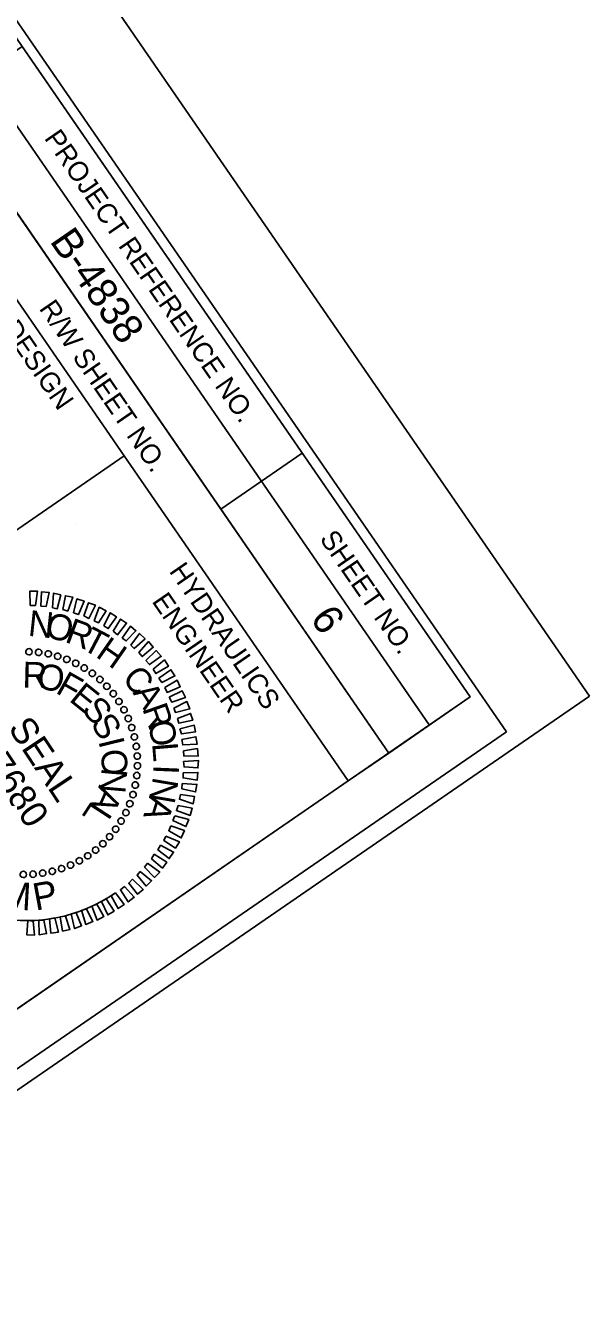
# Model space of a CAD drawing. Extents: x 2297526 to 2298642, y 599613 to 600819.
# Drawn here: x 2298556.7 to 2298642.4, y 599895.5 to 600089.1 of the extents above; entities that cross this region are included whole.
import ezdxf

# ---------------------------------------------------------------- set-up
doc = ezdxf.new("R2010")
doc.units = 0
for name, color, linetype in [('Exist DTM Drainline Cogo Comment', 7, 'Continuous'), ('Exist DTM Drainline Cogo Elevation', 7, 'Continuous'), ('Exist DTM Drainline Cogo Point CELL', 7, 'Continuous'), ('Exist Roads Curbs Cogo Point CELL', 7, 'Continuous'), ('Exist Roads EOP Cogo Point CELL', 7, 'Continuous'), ('Exist Roads Soil Cogo Number', 7, 'Continuous')]:
    doc.layers.add(name, color=color, linetype=linetype)

msp = doc.modelspace()

# ---------------------------------------------------------------- linework, layer by layer
at = {"layer": 'Exist DTM Drainline Cogo Comment'}
msp.add_lwpolyline([(2298629.8, 599981.76), (2298062.67, 600805.27), (2297541.29, 600446.21), (2298108.42, 599622.7)], close=True, dxfattribs=at)
at = {"layer": 'Exist DTM Drainline Cogo Elevation'}
for p, q in [((2298550, 600081.65), (2298618.08, 599982.8)), ((2298543.83, 600077.4), (2298611.91, 599978.54)), ((2298543.83, 600077.4), (2298611.91, 599978.54)), ((2298598.74, 600024.11), (2298586.38, 600015.6)), ((2298611.91, 599978.54), (2298605.73, 599974.29))]:
    msp.add_line(p, q, dxfattribs=at)
for points in [[(2298624.28, 599987.07), (2298113.82, 600728.3), (2297594.96, 600370.97), (2298105.42, 599629.74)], [(2298556.21, 600085.92), (2298624.28, 599987.07), (2298611.91, 599978.54), (2298543.83, 600077.4)], [(2298537.65, 600073.14), (2298571.7, 600023.7), (2298516.11, 599985.42), (2298482.06, 600034.86)], [(2298571.7, 600023.7), (2298605.73, 599974.29), (2298550.14, 599936), (2298516.11, 599985.42)]]:
    msp.add_lwpolyline(points, close=True, dxfattribs=at)
at = {"layer": 'Exist DTM Drainline Cogo Point CELL'}
msp.add_arc((2298556.8, 599977.02), 23.96, 124.5541, 304.5541, dxfattribs=at)
at = {"layer": 'Exist Roads Curbs Cogo Point CELL'}
msp.add_lwpolyline([(2298642.42, 599987.17), (2298069.34, 600819.33), (2297525.77, 600444.99), (2298098.85, 599612.83)], close=True, dxfattribs=at)
at = {"layer": 'Exist Roads Soil Cogo Number'}
for p, q in [((2298564.28, 600013.4), (2298564.28, 600013.4)), ((2298557.23, 599993.95), (2298557.23, 599993.95)), ((2298558.72, 599993.87), (2298558.72, 599993.87)), ((2298560.15, 599993.63), (2298560.15, 599993.63)), ((2298561.62, 599993.29), (2298561.62, 599993.29)), ((2298562.98, 599992.79), (2298562.98, 599992.79)), ((2298564.35, 599992.18), (2298564.35, 599992.18)), ((2298565.65, 599991.47), (2298565.65, 599991.47)), ((2298566.86, 599990.67), (2298566.86, 599990.67)), ((2298568, 599989.73), (2298568, 599989.73)), ((2298569.07, 599988.66), (2298569.07, 599988.66)), ((2298570.06, 599987.58), (2298570.06, 599987.58)), ((2298570.93, 599986.38), (2298570.93, 599986.38)), ((2298571.68, 599985.1), (2298571.68, 599985.1)), ((2298572.31, 599983.77), (2298572.31, 599983.77)), ((2298572.87, 599982.43), (2298572.87, 599982.43)), ((2298573.28, 599980.99), (2298573.28, 599980.99)), ((2298573.55, 599979.54), (2298573.55, 599979.54)), ((2298556.8, 599977.02), (2298556.8, 599977.02)), ((2298573.73, 599976.59), (2298573.73, 599976.59)), ((2298573.74, 599978.07), (2298573.74, 599978.07)), ((2298573.65, 599975.1), (2298573.65, 599975.1)), ((2298573.41, 599973.66), (2298573.41, 599973.66)), ((2298572.57, 599970.83), (2298572.57, 599970.83)), ((2298573.07, 599972.2), (2298573.07, 599972.2)), ((2298571.96, 599969.47), (2298571.96, 599969.47)), ((2298570.45, 599966.95), (2298570.45, 599966.95)), ((2298571.26, 599968.16), (2298571.26, 599968.16)), ((2298568.44, 599964.75), (2298568.44, 599964.75)), ((2298569.51, 599965.82), (2298569.51, 599965.82)), ((2298566.16, 599962.89), (2298566.16, 599962.89)), ((2298567.36, 599963.76), (2298567.36, 599963.76)), ((2298562.21, 599960.95), (2298562.21, 599960.95)), ((2298563.55, 599961.5), (2298563.55, 599961.5)), ((2298564.88, 599962.13), (2298564.88, 599962.13)), ((2298557.85, 599960.08), (2298557.85, 599960.08)), ((2298559.32, 599960.27), (2298559.32, 599960.27)), ((2298560.77, 599960.54), (2298560.77, 599960.54))]:
    msp.add_line(p, q, dxfattribs=at)
for points in [[(2298557.43, 600000.97), (2298557.34, 600003.13), (2298558.51, 600003.15), (2298558.21, 600000.98)], [(2298559.06, 600000.87), (2298559.15, 600003.06), (2298560.29, 600002.95), (2298559.83, 600000.82)], [(2298560.79, 600000.62), (2298560.95, 600002.82), (2298562.07, 600002.57), (2298561.54, 600000.48)], [(2298562.39, 600000.37), (2298562.77, 600002.44), (2298563.9, 600002.23), (2298563.14, 600000.11)], [(2298564.02, 599999.86), (2298564.53, 600001.97), (2298565.63, 600001.62), (2298564.74, 599999.58)], [(2298565.58, 599999.37), (2298566.29, 600001.38), (2298567.32, 600001.02), (2298566.34, 599998.99)], [(2298567.12, 599998.63), (2298567.91, 600000.69), (2298568.95, 600000.14), (2298567.82, 599998.33)], [(2298568.61, 599997.89), (2298569.55, 599999.86), (2298570.53, 599999.26), (2298569.28, 599997.45)], [(2298570.03, 599997.07), (2298571.15, 599998.91), (2298572.06, 599998.3), (2298570.68, 599996.49)], [(2298571.42, 599996.02), (2298572.64, 599997.81), (2298573.49, 599997.12), (2298572.01, 599995.57)], [(2298572.7, 599994.93), (2298574.05, 599996.72), (2298574.89, 599995.91), (2298573.24, 599994.44)], [(2298573.92, 599993.81), (2298575.39, 599995.48), (2298576.11, 599994.62), (2298574.46, 599993.2)], [(2298575.01, 599992.59), (2298576.58, 599994.12), (2298577.34, 599993.25), (2298575.55, 599991.98)], [(2298576.1, 599991.29), (2298577.81, 599992.68), (2298578.42, 599991.74), (2298576.53, 599990.61)], [(2298576.99, 599989.94), (2298578.8, 599991.19), (2298579.41, 599990.25), (2298577.43, 599989.26)], [(2298577.87, 599988.49), (2298579.75, 599989.63), (2298580.22, 599988.6), (2298578.22, 599987.75)], [(2298578.56, 599987.01), (2298580.52, 599987.98), (2298581.01, 599986.97), (2298578.94, 599986.28)], [(2298579.24, 599985.38), (2298581.23, 599986.35), (2298581.66, 599985.25), (2298579.5, 599984.7)], [(2298579.79, 599983.8), (2298581.8, 599984.57), (2298582.12, 599983.51), (2298580, 599983.08)], [(2298580.15, 599982.2), (2298582.35, 599982.77), (2298582.55, 599981.76), (2298580.4, 599981.43)], [(2298580.49, 599980.59), (2298582.61, 599981.02), (2298582.81, 599979.89), (2298580.6, 599979.76)], [(2298580.73, 599978.87), (2298582.83, 599979.21), (2298582.93, 599978.05), (2298580.76, 599978.11)], [(2298580.72, 599977.27), (2298583.01, 599977.4), (2298582.92, 599976.28), (2298580.81, 599976.42)], [(2298580.68, 599975.55), (2298582.91, 599975.58), (2298582.8, 599974.43), (2298580.65, 599974.76)], [(2298580.54, 599973.9), (2298582.77, 599973.76), (2298582.56, 599972.63), (2298580.49, 599973.09)], [(2298579.93, 599970.57), (2298582.06, 599970.15), (2298581.71, 599969.05), (2298579.64, 599969.8)], [(2298580.26, 599972.23), (2298582.39, 599971.94), (2298582.18, 599970.81), (2298580.1, 599971.51)], [(2298579.42, 599968.99), (2298581.52, 599968.43), (2298581.08, 599967.35), (2298579.12, 599968.29)], [(2298578.77, 599967.48), (2298580.85, 599966.74), (2298580.38, 599965.63), (2298578.49, 599966.71)], [(2298578.05, 599965.92), (2298580.09, 599965.03), (2298579.48, 599964.08), (2298577.75, 599965.22)], [(2298576.28, 599963.14), (2298578.17, 599961.94), (2298577.51, 599961.04), (2298575.88, 599962.46)], [(2298577.24, 599964.54), (2298579.2, 599963.47), (2298578.56, 599962.5), (2298576.82, 599963.84)], [(2298575.25, 599961.77), (2298577.11, 599960.44), (2298576.31, 599959.64), (2298574.8, 599961.18)], [(2298572.98, 599959.35), (2298574.61, 599957.81), (2298573.73, 599957.08), (2298572.39, 599958.78)], [(2298574.14, 599960.52), (2298575.88, 599959.13), (2298575.05, 599958.32), (2298573.67, 599959.95)], [(2298570.39, 599957.28), (2298571.72, 599955.53), (2298570.77, 599954.88), (2298569.72, 599956.82)], [(2298571.76, 599958.27), (2298573.23, 599956.61), (2298572.32, 599955.91), (2298571.13, 599957.75)], [(2298567.55, 599955.57), (2298568.61, 599953.68), (2298567.59, 599953.14), (2298566.79, 599955.25)], [(2298568.98, 599956.35), (2298570.17, 599954.51), (2298569.21, 599953.93), (2298568.28, 599955.95)], [(2298557.85, 599952.99), (2298558.09, 599950.86), (2298556.93, 599950.88), (2298557.05, 599953.09)], [(2298559.51, 599953.15), (2298559.91, 599951.09), (2298558.76, 599950.91), (2298558.75, 599953.12)], [(2298561.17, 599953.47), (2298561.72, 599951.31), (2298560.57, 599951.13), (2298560.37, 599953.33)], [(2298562.78, 599953.76), (2298563.46, 599951.69), (2298562.35, 599951.46), (2298561.98, 599953.66)], [(2298564.4, 599954.26), (2298565.22, 599952.29), (2298564.17, 599951.85), (2298563.66, 599954.08)], [(2298565.98, 599954.82), (2298566.95, 599952.94), (2298565.87, 599952.49), (2298565.24, 599954.64)]]:
    msp.add_lwpolyline(points, close=True, dxfattribs=at)
for centre, major_axis in [((2298557.23, 599993.94), (0.012, 0.486)), ((2298558.7, 599993.84), (0.055, 0.483)), ((2298560.16, 599993.61), (0.096, 0.476)), ((2298561.59, 599993.25), (0.138, 0.466)), ((2298562.99, 599992.77), (0.178, 0.452)), ((2298564.34, 599992.17), (0.216, 0.435)), ((2298565.63, 599991.46), (0.254, 0.415)), ((2298566.86, 599990.64), (0.289, 0.391)), ((2298568.01, 599989.71), (0.322, 0.364)), ((2298569.07, 599988.68), (0.352, 0.335)), ((2298570.04, 599987.57), (0.38, 0.303)), ((2298570.91, 599986.37), (0.405, 0.269)), ((2298571.67, 599985.11), (0.427, 0.232)), ((2298572.32, 599983.78), (0.446, 0.194)), ((2298572.85, 599982.4), (0.461, 0.155)), ((2298573.26, 599980.99), (0.472, 0.114)), ((2298573.54, 599979.54), (0.481, 0.072)), ((2298573.7, 599978.07), (0.485, 0.03)), ((2298573.72, 599976.59), (0.486, -0.012)), ((2298573.62, 599975.12), (0.483, -0.055)), ((2298573.04, 599972.22), (0.466, -0.138)), ((2298573.39, 599973.66), (0.476, -0.096)), ((2298572.56, 599970.83), (0.452, -0.178)), ((2298571.24, 599968.19), (0.415, -0.254)), ((2298571.96, 599969.48), (0.435, -0.216)), ((2298570.42, 599966.96), (0.391, -0.289)), ((2298568.46, 599964.75), (0.335, -0.352)), ((2298569.49, 599965.81), (0.364, -0.322)), ((2298564.89, 599962.15), (0.232, -0.427)), ((2298566.16, 599962.91), (0.269, -0.405)), ((2298567.35, 599963.78), (0.303, -0.38)), ((2298559.32, 599960.28), (0.072, -0.481)), ((2298560.77, 599960.56), (0.114, -0.472)), ((2298562.19, 599960.97), (0.155, -0.461)), ((2298563.56, 599961.5), (0.194, -0.446)), ((2298556.37, 599960.09), (-0.012, -0.486)), ((2298557.85, 599960.12), (0.03, -0.485))]:
    msp.add_ellipse(centre, major_axis=major_axis, ratio=0.999708, dxfattribs=at)

# ---------------------------------------------------------------- texts
at = {"layer": 'Exist DTM Drainline Cogo Elevation'}
for s, height, p in [('PROJECT REFERENCE NO.', 3.0001, (2298559.46, 600071.99)), ('ROADWAY DESIGN', 3.0001, (2298540.64, 600061.07)), ('R/W SHEET NO.', 3.0001, (2298558.68, 600046.1)), ('SHEET NO.', 3, (2298601.32, 600011.1)), ('HYDRAULICS', 3, (2298578.45, 600006.17)), ('ENGINEER', 3, (2298575.82, 600001.59))]:
    msp.add_text(s, height=height, rotation=304.5541, dxfattribs=at).set_placement(p)
at = {"layer": 'Exist Roads EOP Cogo Point CELL'}
for s, p in [('B-4838', (2298560.3, 600056.35)), ('6', (2298599.87, 599998.98))]:
    msp.add_text(s, height=4.5, rotation=304.5541, dxfattribs=at).set_placement(p)
at = {"layer": 'Exist Roads Soil Cogo Number'}
for s, height, rotation, p in [('N', 3.93, 353.9776, (2298556.99, 599996.37)), ('O', 3.93, 346.7758, (2298559.49, 599996.2)), ('R', 3.91, 339.5746, (2298562.53, 599995.47)), ('T', 3.88, 332.3738, (2298565.06, 599994.42)), ('H', 3.85, 325.1735, (2298567.22, 599993.25)), ('R', 3.93, 358.5937, (2298556.2, 599988.49)), ('O', 3.93, 349.2353, (2298558.23, 599988.45)), ('F', 3.88, 330.5211, (2298561.13, 599987.75)), ('C', 3.81, 310.7739, (2298571.24, 599989.79)), ('E', 3.84, 321.1651, (2298563.19, 599986.54)), ('A', 3.81, 303.5744, (2298572.92, 599987.71)), ('S', 3.81, 311.8097, (2298565.1, 599985.03)), ('R', 3.83, 289.1752, (2298574.42, 599985.3)), ('SEAL', 4.049, 303.5541, (2298553.97, 599982.32)), ('S', 3.81, 302.4545, (2298566.5, 599983.04)), ('047680', 4.05, 303.5541, (2298547.12, 599981.9)), ('O', 3.86, 281.9752, (2298575.28, 599983.15)), ('I', 3.86, 283.7437, (2298567.76, 599980.38)), ('O', 3.89, 274.3875, (2298568.13, 599979)), ('L', 3.89, 274.7749, (2298575.94, 599979.99)), ('I', 3.92, 267.5742, (2298576.15, 599976.82)), ('N', 3.92, 265.0307, (2298568.31, 599976.38)), ('N', 3.93, 260.373, (2298576.11, 599975.03)), ('A', 3.92, 246.3143, (2298567.95, 599973.8)), ('L', 3.88, 236.9549, (2298566.78, 599971.39)), ('A', 3.93, 253.1712, (2298575.6, 599972.26)), ('M', 4.18, 356.7213, (2298552.83, 599954.87)), ('P', 4.13, 10.5363, (2298558.24, 599954.56))]:
    msp.add_text(s, height=height, rotation=rotation, dxfattribs=at).set_placement(p)

doc.saveas('drawing.dxf')
